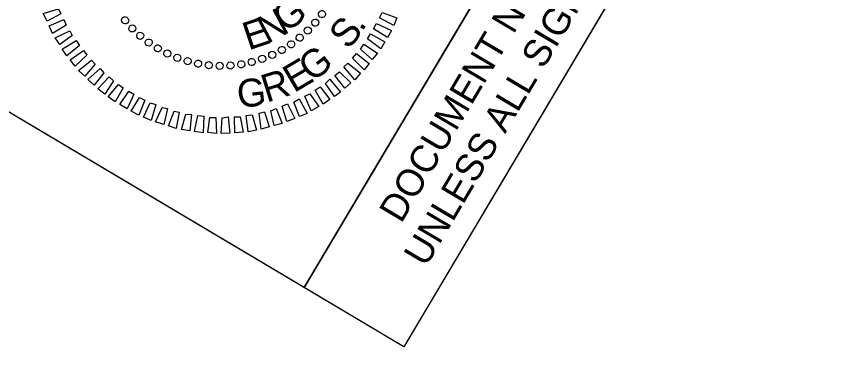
# Model space of a CAD drawing. Extents: x 2138768 to 2143723, y 406633 to 414335.
# Drawn here: x 2141770.8 to 2141936, y 411953.2 to 412025.2 of the extents above; entities that cross this region are included whole.
import ezdxf

# ---------------------------------------------------------------- set-up
doc = ezdxf.new("R2010")
doc.units = 0
for name, color, linetype in [('Prop SBG', 7, 'Continuous'), ('Sheet Clip Boundary CELL', 7, 'Continuous'), ('Sheet Plan And Profile CELL', 7, 'Continuous'), ('Sheet Sticker Exception Certification CELL', 7, 'Continuous')]:
    doc.layers.add(name, color=color, linetype=linetype)

msp = doc.modelspace()

# ---------------------------------------------------------------- linework, layer by layer
at = {"layer": 'Prop SBG'}
for p, q in [((2141792.81, 412024.36), (2141792.81, 412024.36)), ((2141831.35, 412023.92), (2141831.35, 412023.92)), ((2141794.29, 412022.73), (2141794.29, 412022.73)), ((2141829.91, 412022.27), (2141829.91, 412022.27)), ((2141795.96, 412021.22), (2141795.96, 412021.22)), ((2141797.61, 412019.88), (2141797.61, 412019.88)), ((2141828.23, 412020.82), (2141828.23, 412020.82)), ((2141799.46, 412018.67), (2141799.46, 412018.67)), ((2141824.66, 412018.34), (2141824.66, 412018.34)), ((2141826.52, 412019.51), (2141826.52, 412019.51)), ((2141801.4, 412017.63), (2141801.4, 412017.63)), ((2141803.45, 412016.77), (2141803.45, 412016.77)), ((2141820.66, 412016.51), (2141820.66, 412016.51)), ((2141822.68, 412017.36), (2141822.68, 412017.36)), ((2141805.49, 412016.08), (2141805.49, 412016.08)), ((2141807.63, 412015.57), (2141807.63, 412015.57)), ((2141809.79, 412015.28), (2141809.79, 412015.28)), ((2141812.03, 412015.11), (2141812.03, 412015.11)), ((2141814.19, 412015.23), (2141814.19, 412015.23)), ((2141816.41, 412015.43), (2141816.41, 412015.43)), ((2141818.55, 412015.9), (2141818.55, 412015.9))]:
    msp.add_line(p, q, dxfattribs=at)
for points in [[(2141779.86, 412025.7), (2141777.07, 412024.15), (2141776.27, 412025.74), (2141779.39, 412026.68)], [(2141844.91, 412025.95), (2141847.89, 412024.88), (2141847.3, 412023.31), (2141844.38, 412024.87)], [(2141780.93, 412023.38), (2141778.18, 412021.69), (2141777.46, 412023.22), (2141780.45, 412024.54)], [(2141843.8, 412023.69), (2141846.83, 412022.31), (2141845.98, 412020.89), (2141843.19, 412022.66)], [(2141782.12, 412021.27), (2141779.63, 412019.43), (2141778.7, 412020.8), (2141781.65, 412022.25)], [(2141842.58, 412021.63), (2141845.47, 412020.03), (2141844.63, 412018.6), (2141841.96, 412020.59)], [(2141783.62, 412019.28), (2141781.09, 412017.17), (2141780.15, 412018.54), (2141782.93, 412020.27)], [(2141785.11, 412017.28), (2141782.75, 412015.07), (2141781.77, 412016.35), (2141784.42, 412018.27)], [(2141841.21, 412019.52), (2141843.98, 412017.71), (2141842.88, 412016.44), (2141840.51, 412018.54)], [(2141839.73, 412017.61), (2141842.28, 412015.63), (2141841.26, 412014.31), (2141838.94, 412016.68)], [(2141786.82, 412015.45), (2141784.7, 412013.04), (2141783.41, 412014.21), (2141786.06, 412016.31)], [(2141837.99, 412015.67), (2141840.52, 412013.64), (2141839.39, 412012.33), (2141837.19, 412014.92)], [(2141788.59, 412013.71), (2141786.63, 412011.2), (2141785.34, 412012.37), (2141787.82, 412014.57)], [(2141836.25, 412013.91), (2141838.56, 412011.72), (2141837.34, 412010.64), (2141835.36, 412013.21)], [(2141790.54, 412012.08), (2141788.73, 412009.43), (2141787.36, 412010.47), (2141789.63, 412012.91)], [(2141834.32, 412012.43), (2141836.51, 412009.84), (2141835.26, 412008.9), (2141833.45, 412011.55)], [(2141792.5, 412010.68), (2141790.84, 412007.88), (2141789.43, 412008.84), (2141791.52, 412011.38)], [(2141794.66, 412009.4), (2141793.25, 412006.45), (2141791.79, 412007.32), (2141793.62, 412010.02)], [(2141832.37, 412010.91), (2141834.34, 412008.34), (2141832.94, 412007.36), (2141831.37, 412010.21)], [(2141796.86, 412008.21), (2141795.63, 412005.16), (2141794.11, 412005.94), (2141795.78, 412008.74)], [(2141828.1, 412008.43), (2141829.73, 412005.48), (2141828.2, 412004.87), (2141827.02, 412007.79)], [(2141830.24, 412009.49), (2141832.08, 412006.88), (2141830.51, 412006.01), (2141829.24, 412008.98)], [(2141799.11, 412007.29), (2141798.13, 412004.08), (2141796.57, 412004.77), (2141797.95, 412007.68)], [(2141801.43, 412006.49), (2141800.68, 412003.26), (2141799.04, 412003.83), (2141800.39, 412006.7)], [(2141823.47, 412006.52), (2141824.69, 412003.46), (2141823.04, 412003.04), (2141822.38, 412006.06)], [(2141825.76, 412007.43), (2141827.25, 412004.45), (2141825.61, 412003.85), (2141824.67, 412006.97)], [(2141803.81, 412005.78), (2141803.23, 412002.45), (2141801.67, 412002.97), (2141802.77, 412005.99)], [(2141806.31, 412005.28), (2141805.98, 412001.98), (2141804.3, 412002.28), (2141805.19, 412005.36)], [(2141808.78, 412004.93), (2141808.67, 412001.61), (2141806.94, 412001.82), (2141807.57, 412005.06)], [(2141816.18, 412004.84), (2141816.77, 412001.7), (2141815.07, 412001.6), (2141815.01, 412004.84)], [(2141818.61, 412005.2), (2141819.44, 412002.09), (2141817.76, 412001.81), (2141817.39, 412005.11)], [(2141821.08, 412005.84), (2141822.05, 412002.76), (2141820.41, 412002.33), (2141819.99, 412005.56)], [(2141811.21, 412004.71), (2141811.35, 412001.42), (2141809.62, 412001.63), (2141810.04, 412004.7)], [(2141813.71, 412004.79), (2141814.08, 412001.49), (2141812.3, 412001.44), (2141812.55, 412004.61)]]:
    msp.add_lwpolyline(points, close=True, dxfattribs=at)
for centre, major_axis in [((2141832.72, 412025.61), (0.586, -0.421)), ((2141792.87, 412024.35), (-0.558, -0.457)), ((2141831.37, 412023.89), (0.547, -0.47)), ((2141794.33, 412022.72), (-0.516, -0.504)), ((2141829.87, 412022.29), (0.504, -0.516)), ((2141795.93, 412021.22), (-0.47, -0.547)), ((2141828.23, 412020.83), (0.457, -0.558)), ((2141797.65, 412019.86), (-0.421, -0.586)), ((2141826.48, 412019.51), (0.407, -0.596)), ((2141799.49, 412018.66), (-0.368, -0.62)), ((2141801.42, 412017.63), (-0.313, -0.65)), ((2141822.66, 412017.37), (0.297, -0.657)), ((2141824.61, 412018.36), (0.353, -0.629)), ((2141803.43, 412016.76), (-0.255, -0.675)), ((2141805.52, 412016.08), (-0.195, -0.695)), ((2141818.52, 412015.92), (0.178, -0.699)), ((2141820.62, 412016.56), (0.239, -0.681)), ((2141807.65, 412015.58), (-0.134, -0.709)), ((2141809.82, 412015.27), (-0.072, -0.718)), ((2141812.01, 412015.14), (-0.009, -0.721)), ((2141814.2, 412015.21), (0.054, -0.719)), ((2141816.38, 412015.47), (0.117, -0.712))]:
    msp.add_ellipse(centre, major_axis=major_axis, ratio=0.999708, dxfattribs=at)
at = {"layer": 'Sheet Clip Boundary CELL'}
msp.add_lwpolyline([(2141532.03, 410686.07), (2141538.88, 410697.63), (2142265.12, 411921.19), (2142261.89, 411923.11), (2142271.94, 411940.04), (2141951.44, 412130.26), (2141849.34, 411958.24), (2141755.05, 412014.21), (2141652.77, 411841.88), (2141597.82, 411874.49), (2141065.92, 410978.35)], close=True, dxfattribs=at)
at = {"layer": 'Sheet Plan And Profile CELL'}
msp.add_lwpolyline([(2141732.39, 412027.66), (2141783.46, 412113.69), (2141880.2, 412056.27), (2141829.13, 411970.24)], close=True, dxfattribs=at)
at = {"layer": 'Sheet Sticker Exception Certification CELL'}
for p, q in [((2141829.13, 411970.24), (2141931.23, 412142.26)), ((2141951.44, 412130.26), (2141849.34, 411958.24)), ((2141849.34, 411958.24), (2141829.13, 411970.24))]:
    msp.add_line(p, q, dxfattribs=at)

# ---------------------------------------------------------------- texts
at = {"layer": 'Prop SBG'}
for s, rotation, p in [('G', 37.2995, (2141825.49, 412021.69)), ('N', 27.9432, (2141821.62, 412019.5)), ('E', 18.5861, (2141817.85, 412018.24)), ('S', 50.4828, (2141838.06, 412018.25)), ('.', 57.0948, (2141840.82, 412021.91)), ('G', 37.2589, (2141830.72, 412011.7)), ('E', 30.6469, (2141827.06, 412009.58)), ('R', 17.4229, (2141821.52, 412007.66)), ('G', 6.2502, (2141815.83, 412006.59))]:
    msp.add_text(s, height=5.65, rotation=rotation, dxfattribs=at).set_placement(p)
at = {"layer": 'Sheet Sticker Exception Certification CELL'}
for s, p in [('DOCUMENT NOT CONSIDERED FINAL', (2141848.78, 411983.08)), ('UNLESS ALL SIGNATURES COMPLETED', (2141853.76, 411974.22))]:
    msp.add_text(s, height=5.5, rotation=59.3093, dxfattribs=at).set_placement(p)

doc.saveas('drawing.dxf')
